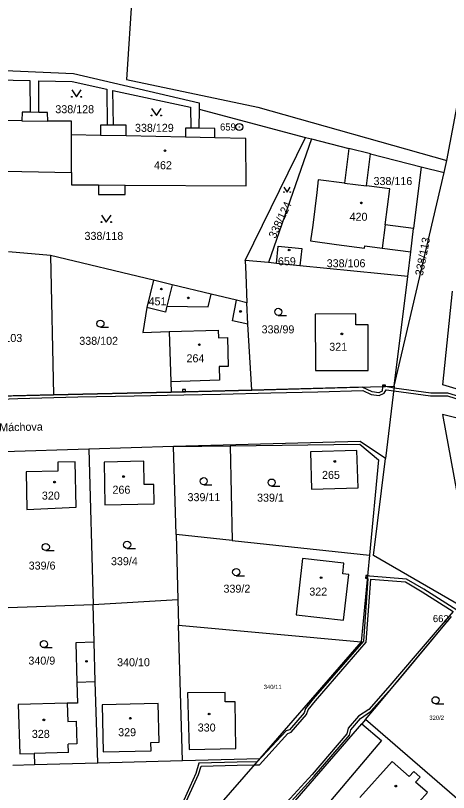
# Model space of a CAD drawing. Extents: x -758582 to -751794, y -998770 to -994350.
# Drawn here: x -755679 to -755587.2, y -995334.3 to -995169.4 of the extents above; entities that cross this region are included whole.
import ezdxf

# ---------------------------------------------------------------- set-up
doc = ezdxf.new("R2010")
doc.units = 0
for name, color, linetype in [('Hranice parcel', 7, 'Continuous'), ('Parcelní čísla', 7, 'Continuous'), ('Pop  PČ popisy', 7, 'Continuous'), ('Vnitřní kresba', 7, 'Continuous'), ('Věcná břemena k části', 7, 'Continuous'), ('Značky bodu BP', 7, 'Continuous'), ('Značky budov', 7, 'Continuous'), ('Značky kultur', 7, 'Continuous')]:
    doc.layers.add(name, color=color, linetype=linetype)

msp = doc.modelspace()

# ---------------------------------------------------------------- linework, layer by layer
at = {"layer": 'Hranice parcel'}
for p, q in [((-755674.12, -995189.92), (-755675.92, -995189.9)), ((-755640.11, -995189.2), (-755640.14, -995193.29)), ((-755640.11, -995189.2), (-755617.54, -995195.22)), ((-755658.27, -995192.62), (-755659.62, -995192.63)), ((-755640.14, -995193.29), (-755641.89, -995193.25)), ((-755667.16, -995202.65), (-755667.16, -995194.69)), ((-755630.31, -995221.33), (-755617.54, -995195.22)), ((-755616.31, -995195.53), (-755625.4, -995221.81)), ((-755617.54, -995195.22), (-755616.31, -995195.53)), ((-755616.31, -995195.53), (-755608.38, -995197.56)), ((-755603.75, -995198.74), (-755608.38, -995197.56)), ((-755603.75, -995198.74), (-755593.04, -995201.48)), ((-755588.16, -995202.7), (-755587.57, -995200.16)), ((-755593.04, -995201.48), (-755594.62, -995214.57)), ((-755593.04, -995201.48), (-755588.16, -995202.7)), ((-755598.72, -995248.04), (-755588.16, -995202.7)), ((-755595.22, -995219.53), (-755594.62, -995214.57)), ((-755623.7, -995221.98), (-755623.34, -995218.3)), ((-755623.34, -995218.3), (-755618.35, -995218.79)), ((-755671.59, -995220.26), (-755680.5, -995219.51)), ((-755649.77, -995225.54), (-755671.59, -995220.26)), ((-755671.59, -995220.26), (-755671.02, -995249.89)), ((-755618.35, -995218.79), (-755618.72, -995222.47)), ((-755595.85, -995224.72), (-755595.22, -995219.53)), ((-755625.4, -995221.81), (-755630.31, -995221.33)), ((-755623.7, -995221.98), (-755625.4, -995221.81)), ((-755618.72, -995222.47), (-755623.7, -995221.98)), ((-755595.85, -995224.72), (-755618.72, -995222.47)), ((-755598.72, -995248.04), (-755595.85, -995224.72)), ((-755649.77, -995225.54), (-755651.18, -995231.37)), ((-755645.85, -995226.49), (-755649.77, -995225.54)), ((-755628.95, -995248.88), (-755598.72, -995248.04)), ((-755598.72, -995248.04), (-755600.61, -995263.4)), ((-755697.93, -995250.53), (-755671.02, -995249.89)), ((-755671.02, -995249.89), (-755646.04, -995249.29)), ((-755646.04, -995249.29), (-755628.95, -995248.88)), ((-755663.53, -995261.43), (-755681.53, -995262.01)), ((-755645.55, -995260.86), (-755663.53, -995261.43)), ((-755663.53, -995261.43), (-755662.59, -995294.42)), ((-755645.55, -995260.86), (-755633.51, -995260.71)), ((-755645.01, -995279.51), (-755645.55, -995260.86)), ((-755633.51, -995260.71), (-755633.09, -995280.78)), ((-755633.09, -995280.78), (-755645.01, -995279.51)), ((-755645.01, -995279.51), (-755644.61, -995293.3)), ((-755633.09, -995280.78), (-755603.97, -995283.89)), ((-755603.97, -995283.89), (-755605.74, -995302.33)), ((-755680.58, -995295), (-755662.59, -995294.42)), ((-755662.59, -995294.42), (-755644.61, -995293.3)), ((-755662.36, -995302.42), (-755662.59, -995294.42)), ((-755644.61, -995293.3), (-755644.45, -995298.79)), ((-755643.63, -995327.53), (-755644.45, -995298.79)), ((-755644.45, -995298.79), (-755605.74, -995302.33)), ((-755605.74, -995302.33), (-755627.2, -995327.12)), ((-755604.83, -995318.78), (-755605.63, -995319.71)), ((-755582.49, -995338.18), (-755604.83, -995318.78)), ((-755622.58, -995339.34), (-755605.63, -995319.71)), ((-755661.62, -995328.01), (-755643.63, -995327.53)), ((-755643.63, -995327.53), (-755627.2, -995327.12)), ((-755627.2, -995327.12), (-755641.82, -995343.72)), ((-755679.62, -995328.48), (-755675.02, -995328.36)), ((-755675.02, -995328.36), (-755661.62, -995328.01))]:
    msp.add_line(p, q, dxfattribs=at)
for points in [[(-755587.57, -995200.16), (-755571.6, -995115.34), (-755567.75, -995086.48), (-755566.92, -995064.43), (-755567.92, -995035.24)], [(-755654.33, -995164.45), (-755655.48, -995182.92), (-755627.63, -995188.77), (-755587.57, -995200.16)], [(-755729.46, -995178.92), (-755666.77, -995181.63), (-755640.08, -995187.88), (-755640.11, -995189.2)], [(-755693.78, -995189.28), (-755693.83, -995182.78), (-755675.99, -995183.17), (-755675.92, -995189.9)], [(-755674.12, -995189.92), (-755674.12, -995183.21), (-755667.02, -995183.36), (-755659.68, -995184.95), (-755659.62, -995192.63)], [(-755658.27, -995192.62), (-755658.38, -995185.23), (-755641.95, -995188.8), (-755641.89, -995193.25)], [(-755695.2, -995189.3), (-755696.42, -995189.24), (-755696.42, -995191.61), (-755703.06, -995191.56), (-755703.06, -995201.94), (-755696.86, -995202.06), (-755696.81, -995203.81), (-755691.78, -995203.81), (-755691.81, -995202.16), (-755667.16, -995202.65)], [(-755675.92, -995189.9), (-755677.66, -995189.88), (-755677.72, -995191.74), (-755690.49, -995191.65), (-755690.49, -995189.24), (-755693.78, -995189.28)], [(-755667.16, -995194.69), (-755667.16, -995191.81), (-755672.19, -995191.78), (-755672.25, -995189.94), (-755674.12, -995189.92)], [(-755659.62, -995192.63), (-755661.03, -995192.65), (-755661.03, -995194.81), (-755667.16, -995194.69)], [(-755667.16, -995202.65), (-755667.16, -995205.29), (-755661.42, -995205.32), (-755661.42, -995207.36), (-755655.81, -995207.36), (-755655.77, -995205.35), (-755630.16, -995205.49), (-755630.22, -995195.43), (-755636.76, -995195.3), (-755636.8, -995193.36), (-755640.14, -995193.29)], [(-755641.89, -995193.25), (-755642.99, -995193.23), (-755642.99, -995195.17), (-755655.56, -995194.92), (-755655.56, -995192.59), (-755658.27, -995192.62)], [(-755608.38, -995197.56), (-755609.3, -995204.92), (-755614.84, -995204.24)], [(-755594.62, -995214.57), (-755600.65, -995213.78), (-755599.66, -995206.13), (-755604.62, -995205.51), (-755603.75, -995198.74)], [(-755614.84, -995204.24), (-755615.17, -995206.95), (-755615.98, -995213.83), (-755616.46, -995217.2)], [(-755616.46, -995217.2), (-755610.96, -995217.98), (-755605.06, -995218.75), (-755605, -995218.26), (-755601.3, -995218.74), (-755595.22, -995219.53)], [(-755630.31, -995221.33), (-755630.22, -995224.29), (-755630.01, -995230.32)], [(-755645.85, -995226.49), (-755646.95, -995231.06), (-755647.26, -995232.32), (-755651.18, -995231.37)], [(-755630.01, -995230.32), (-755632.19, -995229.79), (-755637.54, -995228.5), (-755645.85, -995226.49)], [(-755585.62, -995248.58), (-755588.45, -995247.73), (-755586.35, -995227.86)], [(-755651.18, -995231.37), (-755652.05, -995236.61), (-755646.43, -995236.44), (-755646.12, -995247.09), (-755646.04, -995249.29)], [(-755628.95, -995248.88), (-755629.75, -995234.9), (-755630.01, -995230.32)], [(-755606.88, -995232.71), (-755615.48, -995232.73), (-755615.45, -995244.73), (-755604.24, -995244.7), (-755604.26, -995235), (-755606.88, -995235.01), (-755606.88, -995232.71)], [(-755570.64, -995258.57), (-755588.47, -995254.04), (-755581.92, -995289.89)], [(-755600.61, -995263.4), (-755605.93, -995259.75), (-755645.55, -995260.86)], [(-755633.51, -995260.71), (-755606.03, -995260.37), (-755602.04, -995263.7), (-755603.97, -995283.89)], [(-755616.51, -995261.97), (-755616.26, -995269.93), (-755606.38, -995269.59), (-755606.64, -995261.66), (-755616.51, -995261.97)], [(-755670.08, -995264.18), (-755670.04, -995266.06), (-755676.79, -995266.21), (-755676.61, -995274.24), (-755666.16, -995273.69), (-755666.37, -995264.1), (-755670.08, -995264.18)], [(-755660.26, -995264.16), (-755660.08, -995273.23), (-755649.62, -995273.02), (-755649.7, -995268.88), (-755651.74, -995268.92), (-755651.83, -995263.99), (-755660.26, -995264.16)], [(-755584.69, -995294.66), (-755603.13, -995283.98), (-755600.61, -995263.4)], [(-755618.19, -995284.63), (-755619.54, -995296.55), (-755609.46, -995297.7), (-755608.36, -995288.03), (-755609.65, -995287.88), (-755609.39, -995285.63), (-755618.19, -995284.63)], [(-755604.83, -995318.78), (-755602.92, -995316.56), (-755586.61, -995296.97)], [(-755662.36, -995302.42), (-755666.26, -995302.53), (-755666.02, -995310.88), (-755665.87, -995315.31), (-755668.08, -995315.37), (-755678.45, -995315.6), (-755678.16, -995326.1), (-755675.11, -995326.01), (-755675.02, -995328.36)], [(-755661.62, -995328.01), (-755662.12, -995310.77), (-755662.36, -995302.42)], [(-755632.46, -995315.05), (-755634.56, -995315.07), (-755634.58, -995313.07), (-755642.54, -995313.16), (-755642.24, -995325.19), (-755632.35, -995324.94), (-755632.46, -995315.05)], [(-755648.8, -995315.42), (-755660.7, -995315.7), (-755660.46, -995325.7), (-755650.31, -995325.46), (-755650.35, -995323.66), (-755648.61, -995323.62), (-755648.8, -995315.42)], [(-755605.63, -995319.71), (-755601.43, -995323.27), (-755612.27, -995336.1), (-755601.77, -995344.97), (-755607.9, -995352.23)]]:
    msp.add_lwpolyline(points, dxfattribs=at)
at = {"layer": 'Vnitřní kresba'}
for p, q in [((-755677.72, -995191.74), (-755672.19, -995191.78)), ((-755655.56, -995194.92), (-755661.03, -995194.81)), ((-755636.76, -995195.3), (-755642.99, -995195.17)), ((-755661.42, -995205.32), (-755655.77, -995205.35)), ((-755609.3, -995204.92), (-755604.62, -995205.51)), ((-755600.65, -995213.78), (-755601.3, -995218.74)), ((-755638.2, -995231.22), (-755637.54, -995228.5)), ((-755633, -995234.18), (-755632.19, -995229.79)), ((-755646.95, -995231.06), (-755638.2, -995231.22)), ((-755629.75, -995234.9), (-755633, -995234.18)), ((-755646.43, -995236.44), (-755636.07, -995236.14)), ((-755636.07, -995236.14), (-755636.02, -995237.74)), ((-755636.02, -995237.74), (-755634.12, -995237.69)), ((-755634.12, -995237.69), (-755633.94, -995243.84)), ((-755633.94, -995243.84), (-755635.84, -995243.89)), ((-755635.84, -995243.89), (-755635.76, -995246.79)), ((-755635.76, -995246.79), (-755646.12, -995247.09)), ((-755666.02, -995310.88), (-755662.12, -995310.77)), ((-755668.08, -995315.37), (-755667.98, -995319.22)), ((-755667.98, -995319.22), (-755666.19, -995319.18)), ((-755666.19, -995319.18), (-755666.07, -995323.98)), ((-755666.07, -995323.98), (-755667.87, -995324.02)), ((-755667.83, -995325.81), (-755667.87, -995324.02)), ((-755667.83, -995325.81), (-755675.11, -995326.01)), ((-755599.18, -995327.71), (-755605.99, -995335.38)), ((-755599.18, -995327.71), (-755595.55, -995330.93)), ((-755594.57, -995329.83), (-755595.55, -995330.93)), ((-755593.22, -995331.02), (-755594.57, -995329.83)), ((-755594.2, -995332.13), (-755593.22, -995331.02)), ((-755591.69, -995334.29), (-755594.2, -995332.13)), ((-755593.41, -995336.28), (-755591.69, -995334.29))]:
    msp.add_line(p, q, dxfattribs=at)
at = {"layer": 'Věcná břemena k části'}
for points in [[(-755577.66, -995252.53), (-755587.33, -995249.51), (-755591, -995249.52), (-755598.77, -995248.45), (-755600.59, -995248.09), (-755601.23, -995248.11), (-755601.32, -995249.07), (-755602.02, -995249.42), (-755603.43, -995249.24), (-755605.56, -995248.23), (-755628.95, -995248.88), (-755643.03, -995249.22), (-755643.63, -995249.23), (-755646.04, -995249.29), (-755671.02, -995249.89), (-755693.85, -995250.43)], [(-755687.71, -995250.98), (-755678.53, -995250.63), (-755665.82, -995250.32), (-755653.86, -995250.08), (-755643.33, -995249.87), (-755635.6, -995249.7), (-755624.91, -995249.44), (-755614.92, -995249.22), (-755605.38, -995248.98), (-755603.6, -995249.83), (-755601.92, -995250.04), (-755600.89, -995249.53), (-755600.45, -995248.78), (-755598.84, -995249.04), (-755591.04, -995250.12), (-755587.43, -995250.11), (-755577.85, -995253.1)], [(-755585.48, -995295.61), (-755592.48, -995291.16), (-755596.15, -995288.99), (-755603.93, -995288.38), (-755604.39, -995288.26), (-755604.45, -995288.86), (-755604.3, -995288.87), (-755605.25, -995302.18), (-755615.89, -995314.44), (-755617.52, -995316.46), (-755617.86, -995317.41), (-755620.93, -995320.98), (-755621.67, -995321.24), (-755627.81, -995327.81), (-755632.05, -995327.87), (-755640.15, -995328.11), (-755640.81, -995330.27), (-755644.02, -995337.36)], [(-755643.48, -995337.62), (-755640.25, -995330.48), (-755639.7, -995328.7), (-755632.03, -995328.47), (-755628.34, -995328.42), (-755627.31, -995328.4), (-755621.32, -995321.76), (-755620.58, -995321.49), (-755617.34, -995317.71), (-755616.99, -995316.75), (-755615.43, -995314.83), (-755604.67, -995302.41), (-755603.71, -995289), (-755596.35, -995289.57), (-755592.79, -995291.68), (-755586.22, -995295.85), (-755593.89, -995304.76), (-755600.06, -995312.07), (-755604.15, -995316.69), (-755606.29, -995318.13), (-755608.5, -995320.68), (-755608.78, -995321.82), (-755616.14, -995330.47), (-755621.57, -995336.43)], [(-755621.13, -995336.84), (-755615.69, -995330.87), (-755608.23, -995322.1), (-755607.95, -995320.97), (-755605.89, -995318.58), (-755603.76, -995317.14), (-755598.06, -995310.72), (-755586.61, -995296.97)]]:
    msp.add_lwpolyline(points, dxfattribs=at)
for points in [[(-755601.23, -995248.11), (-755600.59, -995248.09), (-755600.6, -995247.79), (-755601.2, -995247.8)], [(-755643.62, -995248.72), (-755643.63, -995249.23), (-755643.03, -995249.22), (-755643.02, -995248.73)], [(-755604.39, -995288.26), (-755604.75, -995288.23), (-755604.8, -995288.83), (-755604.45, -995288.86)]]:
    msp.add_lwpolyline(points, close=True, dxfattribs=at)
at = {"layer": 'Značky bodu BP'}
for radius in [0.75, 0.03]:
    msp.add_circle((-755631.57, -995193.01), radius, dxfattribs=at)
at = {"layer": 'Značky budov'}
for centre in [(-755647.35, -995198.04), (-755605.7, -995209.13), (-755621.02, -995219.14), (-755648.11, -995227.41), (-755642.4, -995229.29), (-755631.32, -995232.18), (-755609.84, -995236.93), (-755640.05, -995239.23), (-755611.33, -995264.02), (-755656.14, -995267.22), (-755670.77, -995268.41), (-755614.23, -995288.68), (-755663.99, -995306.47), (-755637.98, -995317.64), (-755673.03, -995318.88), (-755654.71, -995318.53), (-755598.4, -995332.95)]:
    msp.add_circle(centre, 0.175, dxfattribs=at)
at = {"layer": 'Značky kultur'}
for p, q in [((-755623.32, -995233.01), (-755621.57, -995233.01)), ((-755661.04, -995235.52), (-755659.29, -995235.52)), ((-755639.13, -995268.96), (-755637.38, -995268.96)), ((-755624.73, -995269.25), (-755622.98, -995269.25)), ((-755672.62, -995282.94), (-755670.87, -995282.94)), ((-755655.37, -995282.47), (-755653.62, -995282.47)), ((-755632.25, -995288.27), (-755630.5, -995288.27)), ((-755673.02, -995303.55), (-755671.27, -995303.55)), ((-755589.97, -995315.46), (-755588.22, -995315.46))]:
    msp.add_line(p, q, dxfattribs=at)
for points in [[(-755667.1, -995185.11), (-755666.1, -995186.61), (-755665.1, -995185.11)], [(-755650.18, -995189.07), (-755649.18, -995190.57), (-755648.18, -995189.07)], [(-755622.12, -995205.82), (-755621.45, -995206.83), (-755620.78, -995205.82)], [(-755660.79, -995211.71), (-755659.79, -995213.21), (-755658.79, -995211.71)]]:
    msp.add_lwpolyline(points, dxfattribs=at)
for centre, radius in [((-755667.1, -995186.61), 0.1), ((-755665.1, -995186.61), 0.1), ((-755650.18, -995190.57), 0.1), ((-755648.18, -995190.57), 0.1), ((-755622.12, -995206.83), 0.067), ((-755620.78, -995206.83), 0.067), ((-755660.79, -995213.21), 0.1), ((-755658.79, -995213.21), 0.1), ((-755623.32, -995232.26), 0.75), ((-755661.04, -995234.77), 0.75), ((-755639.13, -995268.21), 0.75), ((-755624.73, -995268.5), 0.75), ((-755655.37, -995281.72), 0.75), ((-755672.62, -995282.19), 0.75), ((-755632.25, -995287.52), 0.75), ((-755673.02, -995302.8), 0.75), ((-755589.97, -995314.71), 0.75)]:
    msp.add_circle(centre, radius, dxfattribs=at)

# ---------------------------------------------------------------- texts
at = {"layer": 'Parcelní čísla'}
for s, height, p in [('338/128', 1.7, (-755670.6, -995190.09)), ('338/129', 1.7, (-755653.71, -995194.04)), ('462', 1.7, (-755649.67, -995201.98)), ('338/116', 1.7, (-755603.12, -995205.34)), ('420', 1.7, (-755608.2, -995212.92)), ('338/118', 1.7, (-755664.41, -995216.98)), ('659', 1.7, (-755623.4, -995222.37)), ('338/106', 1.7, (-755613.05, -995222.79)), ('451', 1.7, (-755650.83, -995230.88)), ('338/99', 1.7, (-755626.86, -995236.83)), ('338/103', 1.7, (-755685.83, -995238.66)), ('338/102', 1.7, (-755665.52, -995239.26)), ('321', 1.7, (-755612.51, -995240.52)), ('264', 1.7, (-755642.78, -995242.97)), ('265', 1.7, (-755614.05, -995267.73)), ('266', 1.7, (-755658.48, -995270.87)), ('320', 1.7, (-755673.45, -995272.12)), ('339/11', 1.7, (-755642.56, -995272.45)), ('339/1', 1.7, (-755627.82, -995272.56)), ('339/4', 1.7, (-755658.8, -995286.05)), ('339/6', 1.7, (-755676.25, -995286.98)), ('339/2', 1.7, (-755634.94, -995291.88)), ('322', 1.7, (-755616.74, -995292.5)), ('340/9', 1.7, (-755676.31, -995307.15)), ('340/10', 1.7, (-755657.5, -995307.5)), ('340/11', 0.9, (-755626.41, -995312.34)), ('320/2', 0.9, (-755591.29, -995318.88)), ('328', 1.7, (-755675.58, -995322.71)), ('329', 1.7, (-755657.27, -995322.35)), ('330', 1.7, (-755640.4, -995321.36))]:
    msp.add_text(s, height=height, dxfattribs=at).set_placement(p)
for s, rotation, p in [('338/124', 65, (-755623.93, -995216.8)), ('338/113', 79, (-755592.67, -995224.7))]:
    msp.add_text(s, height=1.7, rotation=rotation, dxfattribs=at).set_placement(p)
at = {"layer": 'Pop  PČ popisy'}
msp.add_text('Máchova', height=1.7, rotation=1, dxfattribs=at).set_placement((-755682.48, -995257.63))
at = {"layer": 'Značky bodu BP'}
for s, p in [('659', (-755635.67, -995193.76)), ('662', (-755590.53, -995298.13))]:
    msp.add_text(s, height=1.5, dxfattribs=at).set_placement(p)

doc.saveas('drawing.dxf')
